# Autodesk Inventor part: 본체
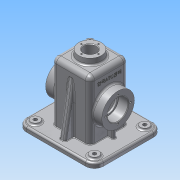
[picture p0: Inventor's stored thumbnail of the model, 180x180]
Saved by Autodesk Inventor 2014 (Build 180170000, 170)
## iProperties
Created: 2015-12
Part Number: 본체
Material: 알루미늄 6061
Document SubType Name: Modeling
Designer: Administrator
Density: 2.71 g/cm^3
Appearance: 알루미늄 - 평지
Mass: 802.731 g
Surface Area: 912.125 cm^2
Volume: 296.211 cm^3
Author: Administrator
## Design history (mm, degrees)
sketch "스케치2"
  geometry: L1 (60, 52.5)-(-60, 52.5); L2 (-60, 52.5)-(-60, -52.5); L3 (-60, -52.5)-(60, -52.5); L4 (60, -52.5)-(60, 52.5); L5 (60, 52.5)-(-60, -52.5); L6 (-60, 52.5)-(60, -52.5); 1 further point
  constraints: 12 end point, 2 midpoint, 2 parallel, 1 horizontal, 1 perpendicular
  dimensions: "d2" = 120 distance of L3.end L2.end; "d3" = 105 distance of L2.end L1.end
extrude "돌출1" new body sketch "스케치2" distance "d4" = 2; taper "d5" = 0 deg
sketch "스케치3"
  geometry: L1 (65, 57.5)-(-65, 57.5); L2 (-65, 57.5)-(-65, -57.5); L3 (-65, -57.5)-(65, -57.5); L4 (65, -57.5)-(65, 57.5); L5 (65, 57.5)-(-65, -57.5); L6 (-65, 57.5)-(65, -57.5); 1 further point
  constraints: 12 end point, 2 midpoint, 2 parallel, 1 horizontal, 1 perpendicular
  dimensions: "d6" = 130 distance of L3.end L2.end; "d7" = 115 distance of L2.end L1.end
extrude "돌출2" join sketch "스케치3" distance "d8" = 8; taper "d9" = 0 deg
fillet "모깎기1" dims "d10" = 10
fillet "모깎기2" dims "d11" = 15
sketch "스케치5"
  geometry: L1 (32.5, 32.5)-(-32.5, 32.5); L2 (-32.5, 32.5)-(-32.5, -32.5); L3 (-32.5, -32.5)-(32.5, -32.5); L4 (32.5, -32.5)-(32.5, 32.5); L5 (32.5, 32.5)-(-32.5, -32.5); L6 (-32.5, 32.5)-(32.5, -32.5); 1 further point
  constraints: 12 end point, 2 midpoint, 2 parallel, 1 horizontal, 1 perpendicular
  dimensions: "d12" = 65 distance of L3.end L2.end; "d13" = 65 distance of L2.end L1.end
extrude "돌출3" join sketch "스케치5" distance "d14" = 100; taper "d15" = 0 deg
sketch "스케치6"
  geometry: L1 (42.5, 0)-(-42.5, 0) reference; C1 r 27.5 at (0, 55); 2 further points
  constraints: 1 centre point, 1 midpoint, 1 vertical alignment
  dimensions: "d16" = 55 diameter of C1; "d17" = 55 distance from line of L1 C1.centre
extrude "돌출4" join sketch "스케치6" stored distance "d18" = 95; taper "d19" = 0 deg
hole "구멍1" diameter "d22" = 30; stored, may be unused: countersink angle "d26" = 90 deg, drill point angle "d28" = 0 deg; dims "d20" = 10, "d21" = 10, "d23" = 6, "d24" = 35, "d25" = 17, "d27" = 57
fillet "모깎기3" dims "d29" = 8
fillet "모깎기4" dims "d30" = 8
sketch "스케치7"
  geometry: C1 r 20 at (0, 0); 1 further point
  constraints: 1 centre point, 1 coincident
  dimensions: "d31" = 40 diameter of C1
extrude "돌출5" join sketch "스케치7" distance "d32" = 10; taper "d33" = -5 deg
sketch "스케치8"
  geometry: L1 (27.5, 27.5)-(-27.5, 27.5); L2 (-27.5, 27.5)-(-27.5, -27.5); L3 (-27.5, -27.5)-(27.5, -27.5); L4 (27.5, -27.5)-(27.5, 27.5); L5 (27.5, 27.5)-(-27.5, -27.5); L6 (-27.5, 27.5)-(27.5, -27.5); 1 further point
  constraints: 12 end point, 2 midpoint, 2 parallel, 1 horizontal, 1 perpendicular
  dimensions: "d34" = 55 distance of L3.end L2.end; "d35" = 55 distance of L2.end L1.end
extrude "돌출6" cut sketch "스케치8" distance "d36" = 105; taper "d37" = 0 deg
fillet "모깎기9" dims "d98" = 3
fillet "모깎기6" dims "d95" = 3
hole "구멍2" diameter "d40" = 21; stored, may be unused: countersink angle "d44" = 90 deg, drill point angle "d46" = 0 deg; dims "d38" = 10, "d39" = 10, "d41" = 6, "d42" = 35, "d43" = 17, "d45" = 50
sketch "스케치10"
  geometry: L1 (-32.5, 10)-(-32.5, 102) reference; L2 (-57.5, 10)-(-42.5, 10) reference; L3 (42.5, 10)-(-42.5, 10) reference; L4 (42.5, 10)-(57.5, 10) reference; L5 (32.5, 102)-(32.5, 10) reference; L6 (47.5, 10)-(32.5, 95.069); L7 (57.5, 10)-(57.5, 2) reference; 4 further points
  constraints: 2 end point, 2 point on line
  dimensions: "d47" = 10 deg angle of L7 L6; "d48" = 10 horizontal distance of L7.end L6.start
feature "리브1" sketch "스케치10" dims "d49" = 1, "d50" = 10, "d51" = 0, "d52" = 0, "d53" = 1, "d54" = 1
sketch "스케치11"
  geometry: L1 (0, 0)-(-21, 0); C1 r 27.5 at (0, 0) reference; 2 further points
  constraints: 2 end point, 1 coincident, 1 horizontal
  dimensions: "d55" = 21 distance of L1.start L1.end
hole "구멍3" sketch "스케치11" at (-21, 0) diameter "d56" = 3.242; stored, may be unused: countersink angle "d60" = 90 deg, drill point angle "d62" = 118 deg; dims "d57" = 8, "d58" = 35, "d59" = 17, "d61" = 10
sketch "스케치13"
  geometry: L1 (0, 0)-(0, 14.5); C1 r 10.5 at (0, 0) reference; 1 further point
  constraints: 2 end point, 1 coincident, 1 vertical
  dimensions: "d66" = 14.5 distance of L1.start L1.end
hole "구멍4" sketch "스케치13" at (0, 14.5) diameter "d67" = 2.459; stored, may be unused: countersink angle "d71" = 90 deg, drill point angle "d73" = 118 deg; dims "d68" = 7, "d69" = 35, "d70" = 17, "d72" = 9
sketch "스케치14"
  geometry: C1 r 7.5 at (-50, 42.5); C2 r 7.5 at (50, 42.5); C3 r 7.5 at (-50, -42.5); C4 r 7.5 at (50, -42.5); A1 r 15 centre (-50, 42.5) between (-50, 57.5) and (-65, 42.5) reference; A2 r 15 centre (-50, -42.5) between (-65, -42.5) and (-50, -57.5) reference; A3 r 15 centre (50, -42.5) between (50, -57.5) and (65, -42.5) reference; A4 r 15 centre (50, 42.5) between (65, 42.5) and (50, 57.5) reference; 1 further point
  constraints: 4 centre point, 4 coincident
  dimensions: "d77" = 15 diameter of C1; "d78" = 15 diameter of C2; "d79" = 15 diameter of C3; "d80" = 15 diameter of C4
extrude "돌출7" join sketch "스케치14" distance "d81" = 3; taper "d82" = 0 deg
sketch "스케치15"
  geometry: C1 r 7.5 at (0, 0) reference; C2 r 7.5 at (-100, 0) reference; C3 r 7.5 at (-100, -85) reference; C4 r 7.5 at (0, -85) reference; 5 further points
  constraints: 4 coincident
hole "구멍5" sketch "스케치15" at (-100, 0), (-100, -85), (0, -85), (0, 0) diameter "d83" = 6; stored, may be unused: countersink angle "d87" = 90 deg, drill point angle "d89" = 0 deg; dims "d84" = 6, "d85" = 4, "d86" = 2, "d88" = 8
fillet "모깎기8" dims "d97" = 3
sketch "스케치18"
  geometry: L1 (-35.5, 27.5)-(-47.5, 27.5) reference; L2 (-32.5, 10)-(-32.5, 102) reference; L3 (-50, 10)-(50, 10) reference; L4 (47.5, 27.5)-(35.5, 27.5) reference; L5 (27.5, 0)-(27.5, 102) reference; L6 (-27.5, 102)-(-27.5, 0) reference; L7 (-42.5, 10)-(-42.5, 27.5); L8 (-27.5, 27.5)-(-27.5, 10); L9 (-42.5, 10)-(-27.5, 10); L10 (-27.5, 27.5)-(-42.5, 27.5); L11 (42.5, 27.5)-(42.5, 10); L12 (27.5, 10)-(42.5, 10); L13 (42.5, 27.5)-(27.5, 27.5); L14 (27.5, 27.5)-(27.5, 10); 2 further points
  constraints: 16 end point, 10 point on line, 3 collinear, 3 parallel, 1 perpendicular
  dimensions: "d100" = 15 distance between parallel lines of L7 L8; "d101" = 15 distance between parallel lines of L14 L11
extrude "돌출9" join sketch "스케치18" stored distance "d102" = 6; taper "d103" = 0 deg
chamfer "모따기1" distance "d104" = 1; stored, may be unused: second distance "d105" = 2, angle "d106" = 45 deg
fillet "모깎기10" dims "d107" = 3
fillet "모깎기11" dims "d108" = 3
fillet "모깎기12" dims "d109" = 3
fillet "모깎기13" dims "d110" = 1
sketch "스케치19"
  geometry: L1 (-18, 5.375)-(-18, 43.625) reference; L2 (0, -8)-(91, -8) reference; A1 r 30.5 centre (47, 24.5) between (28.834, 49) and (28.834, 0) reference; 2 further points
  constraints: 1 horizontal alignment, 1 other
  dimensions: "d111" = 26 distance from line of L1 point (8, 24.5); "d114" = 32.5 distance from line of L2 point (8, 24.5) (derived)
feature "엠보싱1" sketch "스케치19" dims "d112" = 0.5, "d113" = 0
fillet "모깎기14" dims "d115" = 0.3
node "솔리드1"
mirror "대칭1"
mirror "대칭2"
pattern_circular "원형 패턴1" dims angle "d64" = 360 deg
mirror "대칭3"
pattern_circular "원형 패턴2" dims angle "d75" = 360 deg
node "투영된 루프1"
node "투영된 루프2"
node "투영된 루프3"
